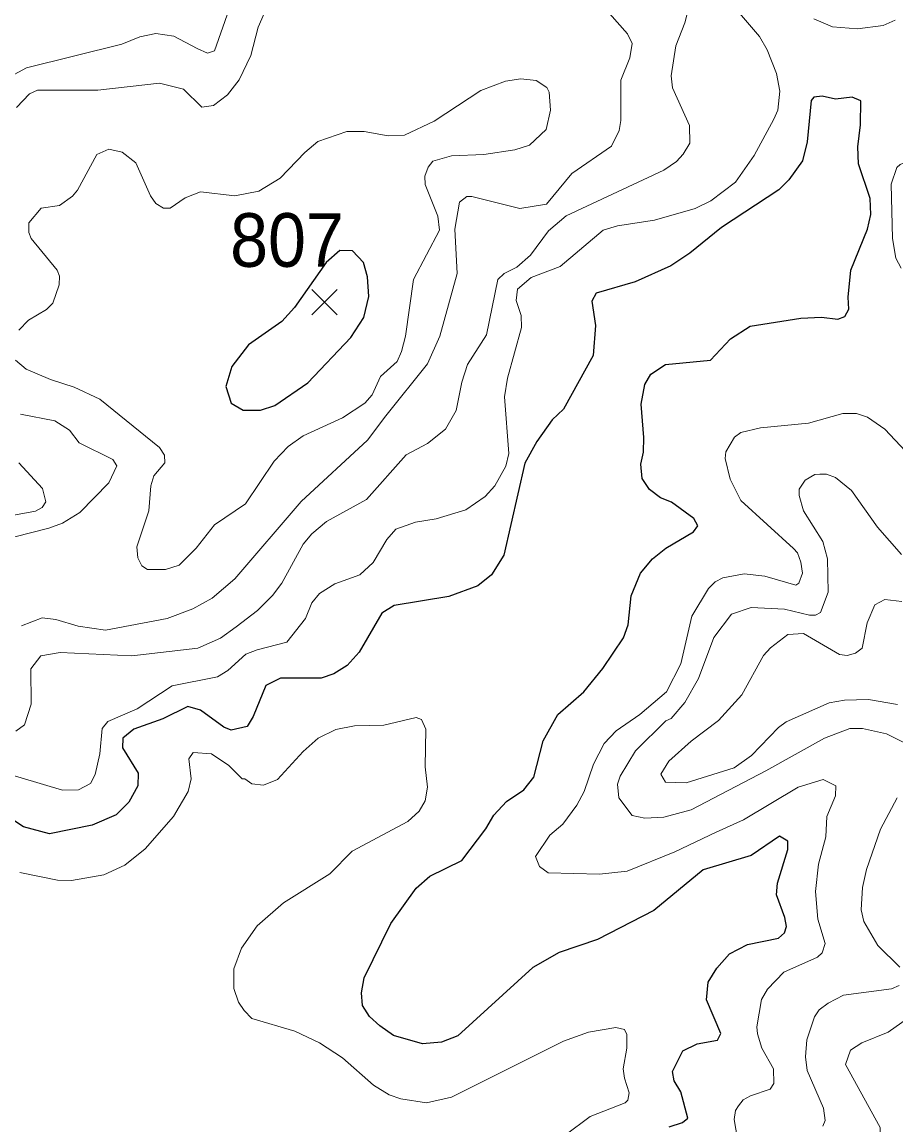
# Model space of a CAD drawing. Extents: x 294.2 to 320.3, y 7482.7 to 7510.7.
# Drawn here: x 314.427 to 315.73, y 7495.414 to 7497.059 of the extents above; entities that cross this region are included whole.
import ezdxf
from ezdxf.enums import TextEntityAlignment as Align

# ---------------------------------------------------------------- set-up
doc = ezdxf.new("R2010")
doc.units = 0
doc.header["$LTSCALE"] = 0.032
for name, color, linetype, lineweight in [('1', 7, 'Continuous', 25), ('2', 7, 'Continuous', 13), ('21', 7, 'Continuous', 25)]:
    doc.layers.add(name, color=color, linetype=linetype, lineweight=lineweight)
doc.layers.add('61', color=7, linetype='Continuous')

msp = doc.modelspace()

# ---------------------------------------------------------------- linework, layer by layer
at = {"layer": '1'}
for points in [[(315.5551, 7495.6928), (315.5638, 7495.7007), (315.5669, 7495.7101), (315.5646, 7495.7235), (315.552, 7495.7573), (315.5536, 7495.7746), (315.5688, 7495.8249), (315.5688, 7495.8375), (315.5564, 7495.845), (315.5141, 7495.8157), (315.4429, 7495.7945), (315.369, 7495.7339), (315.2853, 7495.6907), (315.2279, 7495.671), (315.1889, 7495.649), (315.0769, 7495.5468), (315.0525, 7495.5374), (315.0242, 7495.535), (314.981, 7495.5476), (314.9605, 7495.5617), (314.9452, 7495.5759), (314.9349, 7495.5924), (314.9334, 7495.6113), (314.9373, 7495.6333), (314.977, 7495.7143), (315.0147, 7495.767), (315.0352, 7495.7851), (315.0831, 7495.8087), (315.1189, 7495.8559), (315.1307, 7495.8763), (315.1496, 7495.8967), (315.1755, 7495.914), (315.1904, 7495.9329), (315.204, 7495.9872), (315.226, 7496.0265), (315.2646, 7496.0603), (315.2931, 7496.0949), (315.3238, 7496.1405), (315.3309, 7496.1601), (315.3356, 7496.2034), (315.3492, 7496.2372), (315.3673, 7496.2585), (315.387, 7496.2742), (315.4282, 7496.299), (315.4349, 7496.3076), (315.4287, 7496.3186), (315.3956, 7496.343), (315.3791, 7496.3493), (315.3626, 7496.3619), (315.3516, 7496.3784), (315.35, 7496.3996), (315.354, 7496.4177), (315.3542, 7496.4397), (315.3503, 7496.4893), (315.3558, 7496.5184), (315.3645, 7496.5341), (315.3865, 7496.5483), (315.4537, 7496.5546), (315.4835, 7496.5868), (315.5126, 7496.6057), (315.5885, 7496.6174), (315.6192, 7496.619), (315.6436, 7496.6159), (315.6538, 7496.6198), (315.6601, 7496.6308), (315.6589, 7496.6489), (315.6628, 7496.689), (315.688, 7496.7503), (315.6927, 7496.7723), (315.6915, 7496.7959), (315.6742, 7496.8478), (315.6734, 7496.873), (315.6774, 7496.906), (315.6776, 7496.9416), (315.6651, 7496.9471), (315.6399, 7496.944), (315.6202, 7496.9487), (315.6077, 7496.9471), (315.6037, 7496.9424), (315.5978, 7496.8803), (315.5907, 7496.852), (315.5703, 7496.8237), (315.5554, 7496.8087), (315.47, 7496.7529), (315.4228, 7496.7144), (315.3945, 7496.6955), (315.3413, 7496.6719), (315.2831, 7496.6546), (315.2768, 7496.6428), (315.2823, 7496.6066), (315.2786, 7496.5618), (315.2346, 7496.4816), (315.2175, 7496.4659), (315.1947, 7496.4337), (315.1766, 7496.4014)], [(315.1766, 7496.4014), (315.1455, 7496.2638), (315.127, 7496.2347), (315.1066, 7496.2182), (315.0633, 7496.2025), (314.9819, 7496.1891), (314.9638, 7496.1773)], [(314.9638, 7496.1773), (314.93, 7496.1191), (314.9119, 7496.0995), (314.8919, 7496.0869), (314.873, 7496.0806), (314.8125, 7496.0806), (314.7905, 7496.0696), (314.772, 7496.0232), (314.7626, 7496.0082), (314.739, 7496.0027), (314.728, 7496.0074), (314.6934, 7496.0326), (314.6745, 7496.0381), (314.637, 7496.0199), (314.5937, 7496.0042), (314.5776, 7495.9908), (314.5768, 7495.9767), (314.6004, 7495.9389), (314.5996, 7495.9201), (314.5862, 7495.8957), (314.5674, 7495.8768), (314.5316, 7495.8611), (314.4679, 7495.8485), (314.4294, 7495.8587), (314.4021, 7495.8768)], [(315.469, 7495.5505), (315.4478, 7495.6008), (315.4501, 7495.6268), (315.4631, 7495.648), (315.482, 7495.6693), (315.5087, 7495.6834), (315.5551, 7495.6928)], [(315.3922, 7495.4113), (315.4119, 7495.4176), (315.4198, 7495.4239), (315.4095, 7495.4632), (315.3993, 7495.4797), (315.3972, 7495.4939), (315.4124, 7495.5246), (315.4336, 7495.5348), (315.4643, 7495.5403), (315.469, 7495.5505)]]:
    msp.add_lwpolyline(points, dxfattribs=at)
msp.add_lwpolyline([(314.9176, 7496.5887), (314.937, 7496.6186), (314.9441, 7496.65), (314.9425, 7496.6791), (314.9362, 7496.7004), (314.9197, 7496.7177), (314.9012, 7496.7185), (314.8808, 7496.7004), (314.8336, 7496.6336), (314.8145, 7496.6124), (314.765, 7496.5778), (314.74, 7496.5456), (314.7311, 7496.5157), (314.739, 7496.4905), (314.7567, 7496.4803), (314.7826, 7496.4803), (314.8039, 7496.4874), (314.8534, 7496.5212)], close=True, dxfattribs=at)
at = {"layer": '2'}
for points in [[(315.43, 7497.1928), (315.4192, 7497.1781), (315.4179, 7497.1653), (315.4262, 7497.1181), (315.4249, 7497.0951), (315.4154, 7497.0581), (315.4019, 7497.0236)], [(314.7035, 7497.0127), (314.7143, 7497.0165), (314.736, 7497.0785)], [(315.4971, 7497.0727), (315.5265, 7497.0376), (315.538, 7497.0178), (315.552, 7496.9827), (315.5571, 7496.9559), (315.5539, 7496.9278), (315.5482, 7496.9144), (315.5188, 7496.8601), (315.4907, 7496.8205), (315.4543, 7496.7924), (315.4307, 7496.7809), (315.37, 7496.7637), (315.3151, 7496.7554), (315.2934, 7496.749), (315.2296, 7496.6948), (315.1862, 7496.6781), (315.1657, 7496.6609), (315.1638, 7496.6437), (315.1715, 7496.6214), (315.1721, 7496.6035), (315.151, 7496.5281), (315.1465, 7496.5), (315.1529, 7496.4158), (315.1485, 7496.3966), (315.1319, 7496.3672), (315.1178, 7496.3513), (315.0891, 7496.3314), (315.0444, 7496.3181), (315.0138, 7496.313), (314.9844, 7496.3027), (314.971, 7496.2874), (314.9505, 7496.2529), (314.9307, 7496.2344), (314.8937, 7496.221), (314.8707, 7496.207), (314.8592, 7496.1929), (314.8497, 7496.1693), (314.8222, 7496.1342), (314.7775, 7496.1227), (314.7609, 7496.1163), (314.7341, 7496.092), (314.7188, 7496.0824), (314.6511, 7496.0691), (314.5987, 7496.0346), (314.5553, 7496.016), (314.5464, 7496.0052), (314.5432, 7495.9676), (314.5361, 7495.9369), (314.5292, 7495.9235), (314.5113, 7495.9139), (314.4876, 7495.9133), (314.3587, 7495.9516)], [(315.303, 7497.0721), (315.3298, 7497.0414), (315.3368, 7497.0274), (315.3336, 7497.0057), (315.3202, 7496.9725), (315.3202, 7496.9125), (315.3176, 7496.8972), (315.3062, 7496.8741), (315.2468, 7496.8333), (315.2091, 7496.7873), (315.1696, 7496.7809), (315.098, 7496.7988), (315.0904, 7496.7988), (315.0795, 7496.7905), (315.0725, 7496.7503), (315.0757, 7496.6839), (315.0502, 7496.5907), (315.0316, 7496.5492), (314.9697, 7496.4719), (314.9422, 7496.4355), (314.8433, 7496.3442), (314.7443, 7496.2287), (314.7105, 7496.1999), (314.6818, 7496.184), (314.6435, 7496.1693), (314.5515, 7496.1521), (314.5107, 7496.1578), (314.4775, 7496.168), (314.457, 7496.1705), (314.4264, 7496.1585)], [(314.7685, 7497.0095), (314.7794, 7497.0517), (314.7884, 7497.0721)], [(315.7289, 7497.0619), (315.711, 7497.0542), (315.6727, 7497.0491), (315.6356, 7497.0523), (315.6076, 7497.0638)], [(314.434, 7496.991), (314.5758, 7497.0261), (314.6026, 7497.037), (314.6269, 7497.0421), (314.6537, 7497.0383), (314.6881, 7497.0197), (314.7035, 7497.0127)], [(315.4019, 7497.0236), (315.3949, 7496.9789), (315.3968, 7496.961), (315.4223, 7496.9048), (315.423, 7496.8786), (315.4128, 7496.862), (315.4032, 7496.8512), (315.3841, 7496.8384), (315.2385, 7496.7701), (315.2123, 7496.7478), (315.1855, 7496.7114), (315.1651, 7496.6935), (315.1459, 7496.6839), (315.1364, 7496.675), (315.1197, 7496.5926), (315.0916, 7496.5486), (315.0827, 7496.5218), (315.0744, 7496.4796), (315.0584, 7496.4521), (315.0316, 7496.4304), (314.9997, 7496.4138), (314.941, 7496.3468), (314.881, 7496.3142), (314.8592, 7496.2957), (314.8465, 7496.2804), (314.8145, 7496.2223), (314.8005, 7496.2037), (314.7781, 7496.1814), (314.7462, 7496.1572), (314.7233, 7496.1399), (314.6894, 7496.1252), (314.5911, 7496.1138), (314.4838, 7496.1189), (314.4551, 7496.1138), (314.4404, 7496.0946), (314.441, 7496.0416), (314.4308, 7496.0109), (314.4181, 7496.0014)], [(314.632, 7496.968), (314.6677, 7496.9591), (314.6952, 7496.9323), (314.7124, 7496.9348), (314.7334, 7496.9508), (314.7507, 7496.9731), (314.7685, 7497.0095)], [(314.3919, 7496.9687), (314.434, 7496.991)], [(314.4225, 7496.5996), (314.4366, 7496.6143), (314.4634, 7496.6303), (314.4729, 7496.6398), (314.4825, 7496.6673), (314.4832, 7496.6801), (314.4794, 7496.689), (314.441, 7496.7363), (314.4372, 7496.7452), (314.4372, 7496.7599), (314.4557, 7496.7816), (314.4832, 7496.7854), (314.5023, 7496.7995), (314.51, 7496.8084), (314.5387, 7496.8614), (314.5566, 7496.8697), (314.5764, 7496.8652), (314.5968, 7496.8493), (314.6185, 7496.8001), (314.6268, 7496.7886), (314.6383, 7496.7816), (314.6479, 7496.7816), (314.6703, 7496.7969), (314.6933, 7496.8059), (314.7443, 7496.8001), (314.7801, 7496.8071), (314.812, 7496.8263), (314.849, 7496.8646), (314.8682, 7496.8812), (314.9116, 7496.8959), (314.9372, 7496.8959), (314.9729, 7496.8895), (314.9972, 7496.8907), (315.0419, 7496.9112), (315.1114, 7496.9571), (315.1479, 7496.9712), (315.1708, 7496.9744), (315.1938, 7496.9719), (315.2098, 7496.9616), (315.2129, 7496.9546), (315.2149, 7496.9278), (315.2085, 7496.8991), (315.1836, 7496.8754), (315.1619, 7496.8684), (315.1159, 7496.8614), (315.0674, 7496.8595), (315.0399, 7496.8518), (315.0329, 7496.8429), (315.0278, 7496.8295), (315.0284, 7496.8167), (315.0469, 7496.7695), (315.0495, 7496.749), (315.0106, 7496.675), (314.9991, 7496.5907), (314.9927, 7496.5677), (314.9863, 7496.553), (314.9614, 7496.5306), (314.9493, 7496.5032), (314.9384, 7496.4905), (314.9052, 7496.4687), (314.8465, 7496.4419), (314.8241, 7496.4259), (314.8031, 7496.4042), (314.7602, 7496.3404), (314.7143, 7496.3091), (314.6868, 7496.2746), (314.6613, 7496.2491), (314.6409, 7496.2427), (314.614, 7496.2427), (314.6057, 7496.2478), (314.6, 7496.26), (314.5981, 7496.2765), (314.616, 7496.3302), (314.6192, 7496.3672), (314.6236, 7496.3825), (314.6403, 7496.4017), (314.6396, 7496.4132), (314.632, 7496.4247), (314.5432, 7496.4968), (314.5049, 7496.5147), (314.4698, 7496.5262), (314.4334, 7496.5415), (314.4174, 7496.5549)], [(314.4187, 7496.9317), (314.4385, 7496.9521), (314.45, 7496.9578), (314.54, 7496.9578), (314.632, 7496.968)], [(315.7231, 7496.8174), (315.7314, 7496.8422), (315.7365, 7496.8467), (315.7697, 7496.8601), (315.8004, 7496.8672), (315.9102, 7496.8831), (315.9319, 7496.8838)], [(315.7378, 7496.6922), (315.7301, 7496.7069), (315.725, 7496.7363), (315.7231, 7496.8174)], [(314.4162, 7496.2913), (314.4672, 7496.304), (314.4877, 7496.3117), (314.5132, 7496.3276), (314.5566, 7496.3717), (314.5687, 7496.3972), (314.5623, 7496.4068), (314.5125, 7496.4317), (314.4979, 7496.4502), (314.4762, 7496.4642), (314.4251, 7496.4745)], [(315.4952, 7495.4427), (315.5022, 7495.4516), (315.5131, 7495.4574), (315.5424, 7495.4676), (315.5482, 7495.4759), (315.5475, 7495.4976), (315.5303, 7495.5283), (315.5239, 7495.55), (315.5226, 7495.5602), (315.5296, 7495.6011), (315.5386, 7495.6164), (315.5628, 7495.6419), (315.6133, 7495.6643), (315.6203, 7495.6706), (315.6248, 7495.6847), (315.6139, 7495.7211), (315.6101, 7495.762), (315.6146, 7495.8028), (315.6254, 7495.8437), (315.6273, 7495.8743), (315.6401, 7495.905), (315.6407, 7495.9197), (315.6216, 7495.9292), (315.5846, 7495.9177), (315.5028, 7495.8692), (315.462, 7495.8507), (315.4007, 7495.8213), (315.3292, 7495.7926), (315.2883, 7495.7881), (315.2117, 7495.79), (315.1989, 7495.7996), (315.1925, 7495.8143), (315.2142, 7495.8462), (315.2334, 7495.8628), (315.2545, 7495.8909), (315.2653, 7495.9114), (315.2793, 7495.9522), (315.2953, 7495.9829), (315.3132, 7496.002), (315.3483, 7496.0263), (315.3879, 7496.0601), (315.4096, 7496.1016), (315.4256, 7496.1731), (315.4505, 7496.214), (315.4607, 7496.2242), (315.4722, 7496.23), (315.5041, 7496.2363), (315.5348, 7496.2325), (315.5807, 7496.2191), (315.5852, 7496.2223), (315.5909, 7496.237), (315.5884, 7496.2536), (315.5832, 7496.2676), (315.5775, 7496.274), (315.499, 7496.3455), (315.483, 7496.3775), (315.4754, 7496.4081), (315.4767, 7496.4183), (315.4894, 7496.44), (315.499, 7496.447), (315.5284, 7496.454), (315.5999, 7496.4611), (315.651, 7496.4751), (315.6714, 7496.4751), (315.688, 7496.47), (315.7135, 7496.4521), (315.7908, 7496.3698)], [(314.4008, 7496.3212), (314.4474, 7496.3296), (314.457, 7496.3353), (314.4628, 7496.3436), (314.4576, 7496.3634), (314.4225, 7496.4017)], [(315.6292, 7496.2089), (315.628, 7496.2587), (315.621, 7496.2842), (315.5925, 7496.3301), (315.5857, 7496.353), (315.5857, 7496.3624), (315.5948, 7496.3758), (315.6092, 7496.3841), (315.6167, 7496.3847), (315.6264, 7496.3847), (315.6402, 7496.3797), (315.6637, 7496.3602), (315.7027, 7496.3059), (315.7384, 7496.265)], [(315.4849, 7496.1757), (315.5143, 7496.1859), (315.5641, 7496.1833), (315.6012, 7496.1744), (315.6101, 7496.1744), (315.6177, 7496.1783), (315.6292, 7496.2089)], [(315.7391, 7496.1948), (315.7135, 7496.198), (315.6988, 7496.1897), (315.6874, 7496.1629), (315.6797, 7496.1252), (315.6701, 7496.1176), (315.6574, 7496.1144), (315.6459, 7496.1156), (315.5922, 7496.147), (315.5692, 7496.1457), (315.543, 7496.1259), (315.5328, 7496.1144), (315.5002, 7496.0557), (315.4658, 7496.0173), (315.4249, 7495.9867)], [(315.7557, 7495.9777), (315.7161, 7495.9976), (315.6803, 7496.0052), (315.6612, 7496.0052), (315.6235, 7495.9912), (315.536, 7495.942), (315.4249, 7495.8839), (315.3841, 7495.873), (315.356, 7495.8717), (315.3368, 7495.8756), (315.317, 7495.9018), (315.3151, 7495.9222), (315.3189, 7495.9344), (315.3419, 7495.972), (315.3872, 7496.0167), (315.3949, 7496.0205), (315.4154, 7496.0442), (315.4358, 7496.0799), (315.4588, 7496.1412), (315.4849, 7496.1757)], [(315.515, 7495.965), (315.5552, 7496.0071), (315.5667, 7496.0154), (315.6305, 7496.0435), (315.6535, 7496.0474), (315.6893, 7496.0486), (315.7326, 7496.041)], [(314.8082, 7495.9292), (314.8465, 7495.9713), (314.8688, 7495.9912), (314.895, 7496.0039), (314.9231, 7496.0096), (314.9665, 7496.0103), (315.015, 7496.0218), (315.0227, 7496.0186), (315.029, 7496.0046), (315.0284, 7495.9484), (315.0316, 7495.9178), (315.0284, 7495.8973), (315.0195, 7495.882), (315.0023, 7495.8666), (314.9193, 7495.8226), (314.8861, 7495.7887), (314.8171, 7495.7453), (314.7775, 7495.7109), (314.7545, 7495.6777), (314.743, 7495.647), (314.743, 7495.6177), (314.7501, 7495.5972), (314.7583, 7495.5845), (314.7699, 7495.5729), (314.8337, 7495.5538), (314.8708, 7495.5366), (314.9052, 7495.5142), (314.9512, 7495.4733), (314.9748, 7495.4587), (314.9921, 7495.4529), (315.0304, 7495.4472), (315.0674, 7495.4555), (315.2347, 7495.5391), (315.2717, 7495.5525), (315.3126, 7495.5596), (315.3253, 7495.5563), (315.3291, 7495.5487), (315.3291, 7495.5283), (315.3234, 7495.4976), (315.3253, 7495.4836), (315.3324, 7495.4619), (315.3304, 7495.451), (315.3266, 7495.4472), (315.2743, 7495.4268), (315.2372, 7495.3987)], [(315.4249, 7495.9867), (315.3917, 7495.9567), (315.3796, 7495.9375), (315.3866, 7495.9254), (315.4173, 7495.9241), (315.4888, 7495.9465), (315.515, 7495.965)], [(314.4238, 7495.7907), (314.48, 7495.7792), (314.501, 7495.7785), (314.549, 7495.7869), (314.5802, 7495.8015), (314.6109, 7495.8258), (314.653, 7495.8743), (314.6747, 7495.9114), (314.6792, 7495.9305), (314.676, 7495.9599), (314.6824, 7495.9695), (314.7098, 7495.9675)], [(314.7098, 7495.9675), (314.7353, 7495.9503), (314.7552, 7495.9305), (314.7596, 7495.9305), (314.7698, 7495.9228), (314.7871, 7495.9209), (314.8082, 7495.9292)], [(315.7359, 7495.6496), (315.7033, 7495.6815), (315.6822, 7495.7173), (315.6784, 7495.7351), (315.6803, 7495.7683), (315.6861, 7495.7952), (315.7071, 7495.8552), (315.732, 7495.9018)], [(315.621, 7495.4121), (315.6248, 7495.4204), (315.6222, 7495.4389), (315.5979, 7495.495), (315.5954, 7495.5155), (315.5973, 7495.5411), (315.6088, 7495.5755), (315.6158, 7495.5857), (315.6292, 7495.5959), (315.6522, 7495.6074), (315.7237, 7495.617), (315.7352, 7495.6221)], [(315.7678, 7495.587), (315.7186, 7495.5525), (315.6791, 7495.5366), (315.6624, 7495.5257), (315.6548, 7495.504), (315.7065, 7495.4101), (315.7065, 7495.3833), (315.6918, 7495.3744), (315.6529, 7495.3642), (315.6497, 7495.3597), (315.6484, 7495.3342), (315.6644, 7495.2831), (315.6618, 7495.2575), (315.6535, 7495.2524), (315.6356, 7495.2493), (315.5992, 7495.2511), (315.5929, 7495.248), (315.5871, 7495.2358), (315.5903, 7495.2269), (315.6005, 7495.2199), (315.6382, 7495.2084), (315.6752, 7495.1918), (315.7212, 7495.1599), (315.7486, 7495.1337)], [(315.4498, 7495.3323), (315.483, 7495.3533), (315.4945, 7495.3648), (315.4971, 7495.3757), (315.4888, 7495.4223), (315.4907, 7495.4357), (315.4952, 7495.4427)]]:
    msp.add_lwpolyline(points, dxfattribs=at)
at = {"layer": '21'}
for p, q in [((314.8595, 7496.6602), (314.897, 7496.6227)), ((314.897, 7496.6602), (314.8595, 7496.6227))]:
    msp.add_line(p, q, dxfattribs=at)

# ---------------------------------------------------------------- texts
at = {"layer": '61', "width": 0.95}
msp.add_text('807', height=0.08, dxfattribs=at).set_placement((314.8222, 7496.6941), align=Align.CENTER)

doc.saveas('drawing.dxf')
